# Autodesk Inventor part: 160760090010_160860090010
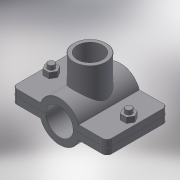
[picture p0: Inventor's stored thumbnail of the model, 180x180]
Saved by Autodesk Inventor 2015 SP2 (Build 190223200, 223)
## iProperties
Created: 2017-05
Part Number: 160760090010_160860090010
Material: Generic
Description: PLASSON SADDLE 90-1"
Document SubType Name: Modeling
Designer: KIM
Density: 1 g/cm^3
Appearance: Default
Author: KIM
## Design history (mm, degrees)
derived "16076.ipt"
feature "Solid1::16076.ipt"
feature "Solid2::16076.ipt"
tag "TaggingFeature1"
body "Solid1"
other parameters: "d0" = 99, "d1" = 141, "d2" = 45, "d4" = 105, "d5" = 0, "d6" = 7.05, "d7" = 141, "d8" = 0.1, "d10" = 0, "d11" = 0.9, "d14" = 39.3783, "d20" = 0.9, "d23" = 0.9, "d36" = 13, "d37" = 10.4, "d38" = 53, "d39" = 0, "d40" = 3, "d41" = 5, "d42" = 0, "d43" = 8, "d44" = 3, "d45" = 0, "d46" = 0.9, "d51" = 75, "d52" = 30.291, "d53" = 21, "d54" = 0, "d55" = 25, "d57" = 0, "d58" = 97.2, "d60" = 0, "d62" = 13, "d63" = 10.4, "d66" = 84.2, "B_" = 25, "G_" = 30.291, "A_" = 75, "L_" = 141, "L_1" = 105, "l_2" = 21
